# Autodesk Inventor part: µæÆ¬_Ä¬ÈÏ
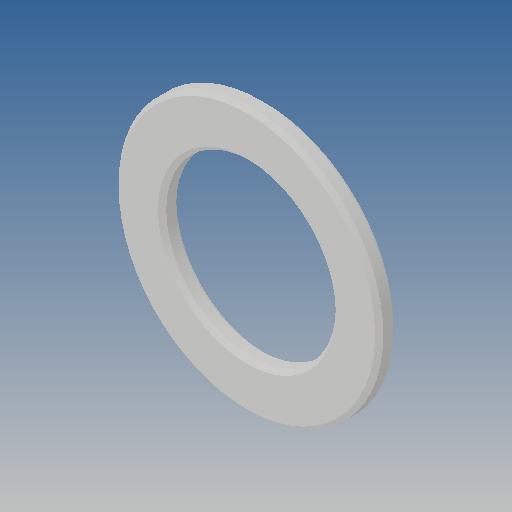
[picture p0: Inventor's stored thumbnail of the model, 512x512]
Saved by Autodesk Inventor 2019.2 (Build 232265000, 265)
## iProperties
Created: 2012-03
Part Number: µæÆ¬_Ä¬ÈÏ
Material: Ogólny
Document SubType Name: Modeling
Designer: CADENGINEERING4
Density: 1 g/cm^3
Appearance: Domyślna
Author: CADENGINEERING4
Revision Number: ÈÎºÎ
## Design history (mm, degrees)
feature "NONE"
node "Bryła1"
